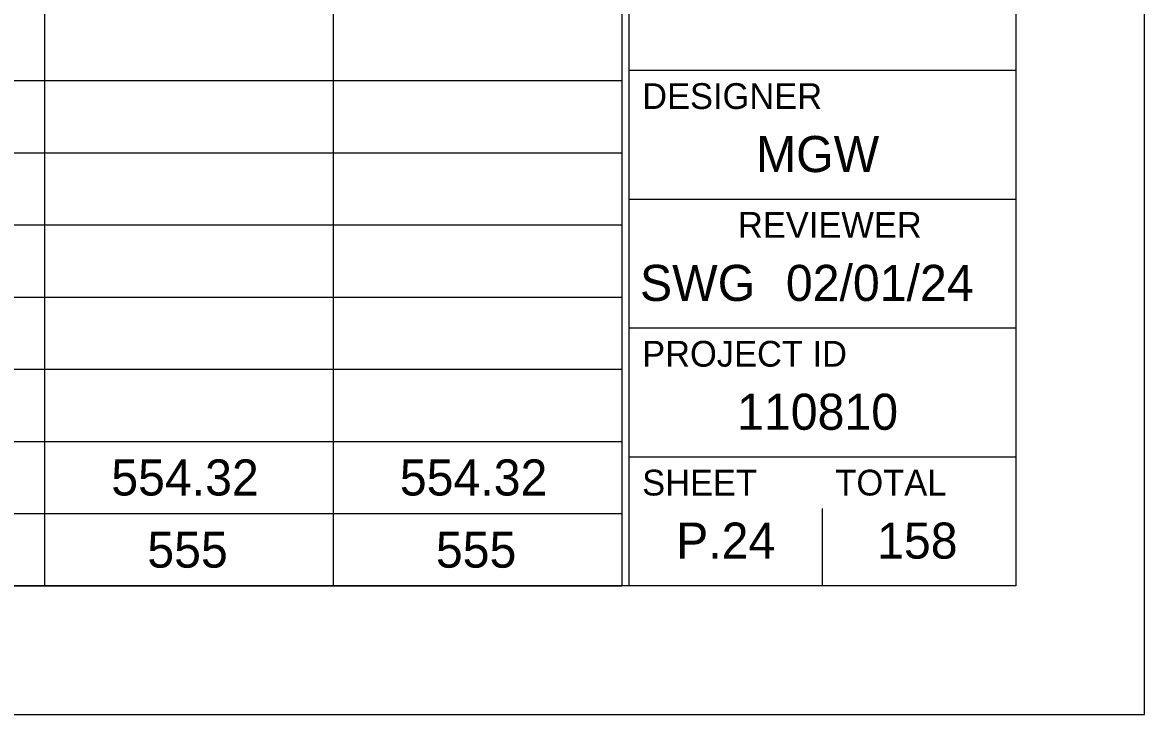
# Model space of a CAD drawing. Extents: x 0 to 34, y 0 to 22.
# Drawn here: x 29.645 to 34, y 0 to 2.686 of the extents above; entities that cross this region are included whole.
import ezdxf

# ---------------------------------------------------------------- set-up
doc = ezdxf.new("R2010")
doc.units = 0
for name, color, linetype in [('SH_Border', 7, 'Continuous'), ('SH_Cut_Line', 7, 'Continuous'), ('SH_Data', 7, 'Continuous'), ('SH_Text', 7, 'Continuous')]:
    doc.layers.add(name, color=color, linetype=linetype)

msp = doc.modelspace()

# ---------------------------------------------------------------- linework, layer by layer
at = {"layer": 'SH_Border'}
for p, q in [((32, 0.5), (32, 21.5)), ((32, 2.5), (33.5, 2.5)), ((32, 2), (33.5, 2)), ((32, 1.5), (33.5, 1.5)), ((32, 1), (33.5, 1))]:
    msp.add_line(p, q, dxfattribs=at)
msp.add_lwpolyline([(1.5, 21.5), (33.5, 21.5), (33.5, 0.5), (1.5, 0.5)], close=True, dxfattribs=at)
at = {"layer": 'SH_Cut_Line'}
msp.add_lwpolyline([(0, 0), (34, 0), (34, 22), (0, 22)], close=True, dxfattribs=at)
at = {"layer": 'SH_Data'}
for p, q in [((29.7306, 21.5), (29.7306, 0.5)), ((30.8506, 21.5), (30.8506, 0.5)), ((31.9706, 21.5), (31.9706, 0.5)), ((1.5, 2.46), (31.9706, 2.46)), ((1.5, 2.18), (31.9706, 2.18)), ((1.5, 1.9), (31.9706, 1.9)), ((1.5, 1.62), (31.9706, 1.62)), ((1.5, 1.34), (31.9706, 1.34)), ((1.5, 1.06), (31.9706, 1.06)), ((32.75, 0.5), (32.75, 0.8)), ((1.5, 0.78), (31.9706, 0.78)), ((32.375, 0.675), (32.375, 0.675)), ((1.5, 0.5), (31.9706, 0.5))]:
    msp.add_line(p, q, dxfattribs=at)

# ---------------------------------------------------------------- texts
for s, height, p in [('DESIGNER', 0.1, (32.05, 2.35)), ('MGW', 0.14, (32.4918, 2.105)), ('REVIEWER', 0.1, (32.4218, 1.85)), ('SWG', 0.14, (32.0416, 1.605)), ('02/01/24', 0.14, (32.6078, 1.605)), ('PROJECT ID', 0.1, (32.05, 1.35)), ('110810', 0.14, (32.4186, 1.105)), ('SHEET', 0.1, (32.05, 0.85)), ('TOTAL', 0.1, (32.8, 0.85)), ('P.24', 0.14, (32.1816, 0.605)), ('158', 0.14, (32.9619, 0.605))]:
    msp.add_text(s, height=height, dxfattribs=at).set_placement(p)
at = {"layer": 'SH_Text'}
for s, p in [('554.32', (29.9895, 0.85)), ('554.32', (31.1095, 0.85)), ('555', (30.1294, 0.57)), ('555', (31.2494, 0.57))]:
    msp.add_text(s, height=0.14, dxfattribs=at).set_placement(p)

doc.saveas('drawing.dxf')
